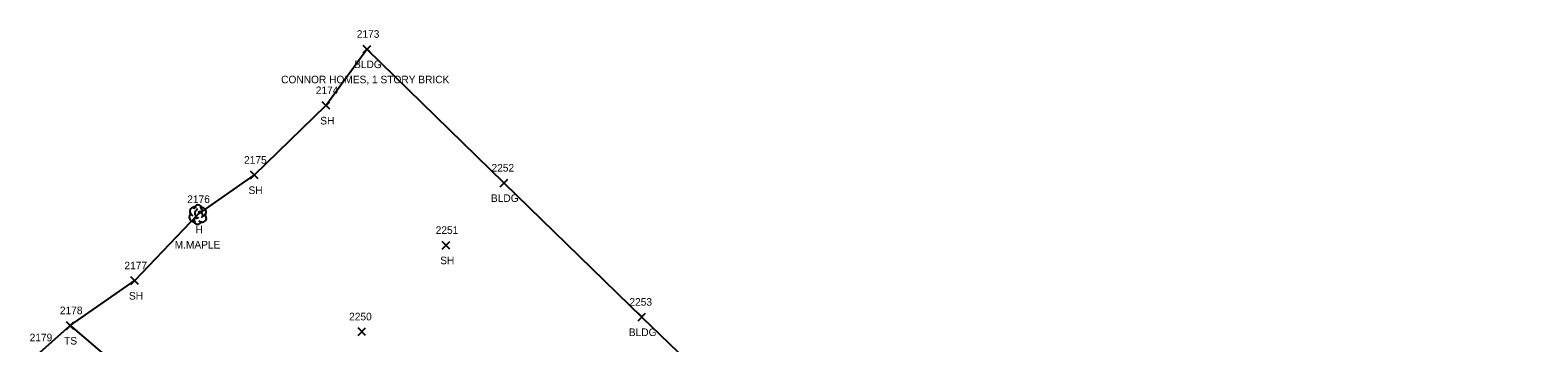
# Model space of a CAD drawing. Extents: x 1472233 to 1475777, y 540726 to 543442.
# Drawn here: x 1473523.1 to 1473920, y 542800 to 542882.5 of the extents above; entities that cross this region are included whole.
import ezdxf

# ---------------------------------------------------------------- set-up
doc = ezdxf.new("R2010")
doc.units = 0
for name, color, linetype in [('L_A', 7, 'Continuous'), ('L_C', 7, 'Continuous'), ('L_I', 7, 'Continuous'), ('L_TIC', 7, 'Continuous'), ('LBC', 7, 'Continuous'), ('LELB', 7, 'Continuous'), ('LSOGP', 7, 'Continuous'), ('LTD', 7, 'Continuous')]:
    doc.layers.add(name, color=color, linetype=linetype)

msp = doc.modelspace()

# ---------------------------------------------------------------- linework, layer by layer
at = {"layer": 'L_TIC'}
for points in [[(1473610.81, 542876.43), (1473612.81, 542878.43)], [(1473612.81, 542876.43), (1473610.81, 542878.43)], [(1473600.01, 542861.58), (1473602.01, 542863.58)], [(1473602.01, 542861.58), (1473600.01, 542863.58)], [(1473581.14, 542843.23), (1473583.14, 542845.23)], [(1473583.14, 542843.23), (1473581.14, 542845.23)], [(1473646.84, 542841.15), (1473648.84, 542843.15)], [(1473648.84, 542841.15), (1473646.84, 542843.15)], [(1473631.59, 542824.73), (1473633.59, 542826.73)], [(1473633.59, 542824.73), (1473631.59, 542826.73)], [(1473549.66, 542815.39), (1473551.66, 542817.39)], [(1473551.66, 542815.39), (1473549.66, 542817.39)], [(1473532.67, 542803.55), (1473534.67, 542805.55)], [(1473534.67, 542803.55), (1473532.67, 542805.55)], [(1473683.15, 542805.79), (1473685.15, 542807.79)], [(1473685.15, 542805.79), (1473683.15, 542807.79)], [(1473609.46, 542801.93), (1473611.46, 542803.93)], [(1473611.46, 542801.93), (1473609.46, 542803.93)]]:
    msp.add_lwpolyline(points, dxfattribs=at)
at = {"layer": 'LBC'}
msp.add_lwpolyline([(1473611.81, 542877.43), (1473647.84, 542842.15), (1473684.15, 542806.79), (1473712.79, 542779.19), (1473741.79, 542750.87), (1473773.96, 542719.66), (1473804, 542690.56), (1473836.45, 542659.06), (1473871.86, 542624.85), (1473901.94, 542656.08), (1473913.55, 542668.06), (1473934.21, 542647.92), (1473934.79, 542648.35), (1473977.15, 542693.11), (1473991.17, 542706.54), (1473991.24, 542706.56), (1473999.37, 542698.9), (1474013.8, 542713.45), (1473985.08, 542741.69), (1474015.74, 542773.16), (1474040.72, 542798.97), (1474028.75, 542810.8)], dxfattribs=at)
at = {"layer": 'LELB'}
msp.add_lwpolyline([(1473533.67, 542804.55), (1473552.88, 542788.13), (1473556.88, 542785.23), (1473573.99, 542766.25), (1473612.39, 542727.62), (1473636.32, 542702.27), (1473673.71, 542668.77), (1473704.07, 542641.06), (1473731.53, 542612.73), (1473761.48, 542585.32), (1473782.29, 542564.92), (1473785.92, 542561.45), (1473799.65, 542550.04), (1473837.85, 542540.63), (1473852.25, 542543.24), (1473872.66, 542564.42), (1473894.27, 542588.71), (1473912.61, 542619.34)], dxfattribs=at)
at = {"layer": 'LSOGP'}
msp.add_lwpolyline([(1473525.71, 542797.41), (1473533.67, 542804.55), (1473550.66, 542816.39), (1473567.25, 542833.87), (1473582.14, 542844.23), (1473601.01, 542862.58), (1473611.81, 542877.43), (1473647.84, 542842.15), (1473684.15, 542806.79), (1473712.79, 542779.19)], dxfattribs=at)
at = {"layer": 'LTD'}
msp.add_line((1473567.25, 542833.87), (1473567.25, 542833.87), dxfattribs=at)
msp.add_line((1473567.25, 542833.87), (1473567.25, 542833.87), dxfattribs=at)
msp.add_arc((1473567.3, 542835.3), 1.05, 335.5272, 180.9563, dxfattribs=at)
for centre, major_axis, ratio, start_param, end_param in [((1473566.46, 542834.54), (1.21, -0.51), 0.895232, 1.570796, 4.712389), ((1473568.29, 542834.45), (-1.14, -0.48), 0.949671, 1.570796, 4.712389), ((1473566.17, 542833.16), (0.58, -1.04), 0.959034, 3.141593, 6.283185), ((1473567.25, 542832.37), (0.26, 1.06), 0.942809, 1.570796, 4.712389), ((1473566.79, 542833.12), (-0.625, -0.083), 0.423636, 0, 3.141593), ((1473567.04, 542834.33), (-0.208, -0.792), 0.645439, 3.141593, 6.283185), ((1473567.75, 542833.7), (-0.5, 0.667), 0.989748, 3.141593, 6.283185), ((1473568.25, 542833.04), (-1.09, 0.79), 0.841452, 1.570796, 4.712389)]:
    msp.add_ellipse(centre, major_axis=major_axis, ratio=ratio, start_param=start_param, end_param=end_param, dxfattribs=at)

# ---------------------------------------------------------------- texts
at = {"layer": 'L_A'}
for s, p in [('BLDG', (1473608.4, 542872.43)), ('SH', (1473599.5, 542857.58)), ('SH', (1473580.63, 542839.23)), ('BLDG', (1473644.44, 542837.15)), ('H', (1473566.68, 542828.87)), ('SH', (1473631.08, 542820.73)), ('SH', (1473549.14, 542811.39)), ('TS', (1473532.08, 542799.55)), ('BLDG', (1473680.74, 542801.79))]:
    msp.add_text(s, height=2, dxfattribs=at).set_placement(p)
at = {"layer": 'L_C'}
for s, p in [('CONNOR HOMES, 1 STORY BRICK', (1473589.21, 542868.43)), ('M.MAPLE', (1473561.19, 542824.87))]:
    msp.add_text(s, height=2, dxfattribs=at).set_placement(p)
at = {"layer": 'L_I'}
for s, p in [('2173', (1473609.12, 542880.43)), ('2174', (1473598.32, 542865.58)), ('2175', (1473579.45, 542847.23)), ('2252', (1473644.59, 542845.15)), ('2176', (1473564.5, 542836.87)), ('2251', (1473629.9, 542828.73)), ('2177', (1473547.96, 542819.39)), ('2178', (1473530.97, 542807.55)), ('2253', (1473680.89, 542809.79)), ('2250', (1473607.11, 542805.93)), ('2179', (1473523.01, 542800.41))]:
    msp.add_text(s, height=2, dxfattribs=at).set_placement(p)

doc.saveas('drawing.dxf')
